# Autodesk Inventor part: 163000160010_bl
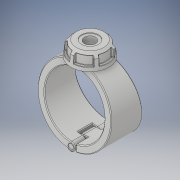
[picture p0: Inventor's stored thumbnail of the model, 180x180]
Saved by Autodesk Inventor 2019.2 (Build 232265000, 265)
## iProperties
Created: 2022-02
Part Number: 163000160010_bl
Material: Generic
Description: Plassadle Threaded 160x1''
Document SubType Name: Modeling
Designer: comp2
Density: 1 g/cm^3
Appearance: Default
Author: comp2
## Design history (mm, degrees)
derived "16300.ipt"
feature "Solid1::16300.ipt" dims "ScaleForDerivedMember" = 10
feature "Solid2::16300.ipt" dims "ScaleForDerivedMember" = 10
feature "Solid3::16300.ipt" dims "ScaleForDerivedMember" = 10
feature "Solid4::16300.ipt" dims "ScaleForDerivedMember" = 10
tag "TaggingFeature1"
body "Solid1"
body "Solid2"
body "Solid3"
body "Solid4"
other parameters: "d2" = 197 [user parameter], "d7" = 187.15 [user parameter], "d8" = 85 deg [user parameter], "d9" = 45 deg [user parameter], "d10" = 102 [user parameter], "d11" = 49 [user parameter], "d12" = 27.2895 [user parameter], "d13" = 42.84 [user parameter], "d14" = 45.4365 [user parameter], "d42" = 3.7 [user parameter], "d49" = 3.94 [user parameter], "d50" = 106 [user parameter], "d51" = 0 [user parameter], "d52" = 25.9 [user parameter], "d53" = 108.35 [user parameter], "d54" = 37.1 [user parameter], "d55" = 0 [user parameter], "d56" = 21.2 [user parameter], "d57" = 21.2 [user parameter], "d59" = 0 [user parameter], "d60" = 106 [user parameter], "d61" = 0 [user parameter], "d62" = 37.1 [user parameter], "d63" = 0 [user parameter], "d65" = 0 [user parameter], "d67" = 0 [user parameter], "d69" = 0 [user parameter], "d70" = 1 [user parameter], "d71" = 101.76 [user parameter], "d72" = 0 [user parameter], "d73" = 2 [user parameter], "d78" = 86.7 [user parameter], "d79" = 5.1 [user parameter], "d80" = 60 deg [user parameter], "d81" = 5.1 [user parameter], "d84" = 0 [user parameter], "d85" = 1 [user parameter], "d87" = 360 deg [user parameter], "d122" = 49 [user parameter], "d124" = 42.80128 [user parameter], "d125" = 1.94925 [user parameter], "d127" = 235 [user parameter], "d129" = 30.291 [user parameter], "d130" = 25.74735 [user parameter], "d131" = 31.85 [user parameter], "d132" = 45 deg [user parameter], "d133" = 22.295 [user parameter], "d134" = 15.1455 [user parameter], "d136" = 0 [user parameter], "d138" = 0 [user parameter], "d1" = 25 [user parameter], "B" = 197 [user parameter], "L" = 106 [user parameter], "E_" = 54 [user parameter], "E1" = 102 [user parameter], "H1" = 235 [user parameter], "H2" = 49 [user parameter], "H3" = 78 [user parameter], "H_costum" = 49 [user parameter], "Rp" = 30.291 [user parameter], "d128" = 38.985 [user parameter]
